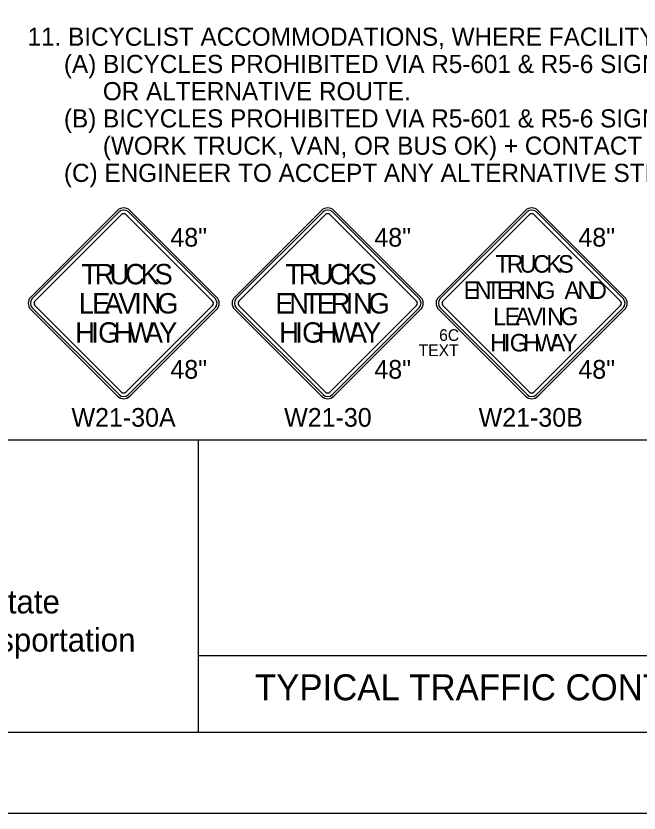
# Model space of a CAD drawing. Extents: x 99999 to 100116, y 99995 to 100013.
# Drawn here: x 100011.504 to 100013.904, y 99999.687 to 100002.761 of the extents above; entities that cross this region are included whole.
import ezdxf

# ---------------------------------------------------------------- set-up
doc = ezdxf.new("R2010")
doc.units = 0
for name, color, linetype in [('SH_GI_GeneralNotesBodyText', 7, 'Continuous'), ('SH_GI_PlotLimits', 7, 'Continuous'), ('SH_GI_SheetBorder', 7, 'Continuous'), ('SH_GI_SheetTextInCells', 7, 'Continuous'), ('SH_GI_TitleBlockText', 7, 'Continuous'), ('TR_SN_ConstructionSigns', 7, 'Continuous')]:
    doc.layers.add(name, color=color, linetype=linetype)

msp = doc.modelspace()

# ---------------------------------------------------------------- linework, layer by layer
at = {"layer": 'SH_GI_PlotLimits'}
msp.add_lwpolyline([(99999.0625, 99999.6875), (100016.0625, 99999.6875), (100016.0625, 100010.6875), (99999.0625, 100010.6875)], close=True, dxfattribs=at)
at = {"layer": 'SH_GI_SheetBorder'}
for p, q in [((100000, 100001.1259), (100015.75, 100001.1259)), ((100012.2055, 100001.1259), (100012.2055, 100000)), ((100012.2055, 100000.2955), (100015.2079, 100000.2955)), ((100000, 100000), (100015.75, 100000))]:
    msp.add_line(p, q, dxfattribs=at)
at = {"layer": 'TR_SN_ConstructionSigns'}
for p, q in [((100011.8955, 100002.0107), (100011.5613, 100001.6766)), ((100011.9014, 100002.0048), (100011.5673, 100001.6707)), ((100011.5773, 100001.6607), (100011.9114, 100001.9948)), ((100011.9273, 100001.9948), (100012.2614, 100001.6607)), ((100012.2713, 100001.6707), (100011.9372, 100002.0048)), ((100012.2773, 100001.6766), (100011.9432, 100002.0107)), ((100012.6812, 100002.0107), (100012.3471, 100001.6766)), ((100012.6871, 100002.0048), (100012.353, 100001.6707)), ((100012.363, 100001.6607), (100012.6971, 100001.9948)), ((100012.713, 100001.9948), (100013.0471, 100001.6607)), ((100013.057, 100001.6707), (100012.7229, 100002.0048)), ((100013.063, 100001.6766), (100012.7289, 100002.0107)), ((100013.4669, 100002.0107), (100013.1328, 100001.6766)), ((100013.4729, 100002.0048), (100013.1387, 100001.6707)), ((100013.1487, 100001.6607), (100013.4828, 100001.9948)), ((100013.4987, 100001.9948), (100013.8328, 100001.6607)), ((100013.8428, 100001.6707), (100013.5087, 100002.0048)), ((100013.8487, 100001.6766), (100013.5146, 100002.0107)), ((100011.5613, 100001.6289), (100011.8955, 100001.2948)), ((100011.5673, 100001.6349), (100011.9014, 100001.3008)), ((100011.9114, 100001.3107), (100011.5773, 100001.6448)), ((100012.2614, 100001.6448), (100011.9273, 100001.3107)), ((100011.9372, 100001.3008), (100012.2713, 100001.6349)), ((100011.9432, 100001.2948), (100012.2773, 100001.6289)), ((100012.3471, 100001.6289), (100012.6812, 100001.2948)), ((100012.353, 100001.6349), (100012.6871, 100001.3008)), ((100012.6971, 100001.3107), (100012.363, 100001.6448)), ((100013.0471, 100001.6448), (100012.713, 100001.3107)), ((100012.7229, 100001.3008), (100013.057, 100001.6349)), ((100012.7289, 100001.2948), (100013.063, 100001.6289)), ((100013.1328, 100001.6289), (100013.4669, 100001.2948)), ((100013.1387, 100001.6349), (100013.4729, 100001.3008)), ((100013.4828, 100001.3107), (100013.1487, 100001.6448)), ((100013.8328, 100001.6448), (100013.4987, 100001.3107)), ((100013.5087, 100001.3008), (100013.8428, 100001.6349)), ((100013.5146, 100001.2948), (100013.8487, 100001.6289))]:
    msp.add_line(p, q, dxfattribs=at)
for centre, radius, start, end in [((100011.9193, 100001.9869), 0.0338, 45, 135), ((100011.9193, 100001.9869), 0.0253, 45, 135), ((100011.9193, 100001.9869), 0.0113, 45, 135), ((100012.705, 100001.9869), 0.0338, 45, 135), ((100012.705, 100001.9869), 0.0253, 45, 135), ((100012.705, 100001.9869), 0.0113, 45, 135), ((100013.4908, 100001.9869), 0.0338, 45, 135), ((100013.4908, 100001.9869), 0.0253, 45, 135), ((100013.4908, 100001.9869), 0.0113, 45, 135), ((100011.5852, 100001.6528), 0.0338, 135, 225), ((100011.5852, 100001.6528), 0.0253, 135, 225), ((100011.5852, 100001.6528), 0.0113, 135, 225), ((100012.2534, 100001.6528), 0.0113, 315, 45), ((100012.2534, 100001.6528), 0.0253, 315, 45), ((100012.2534, 100001.6528), 0.0338, 315, 45), ((100012.3709, 100001.6528), 0.0338, 135, 225), ((100012.3709, 100001.6528), 0.0253, 135, 225), ((100012.3709, 100001.6528), 0.0113, 135, 225), ((100013.0391, 100001.6528), 0.0113, 315, 45), ((100013.0391, 100001.6528), 0.0253, 315, 45), ((100013.0391, 100001.6528), 0.0338, 315, 45), ((100013.1566, 100001.6528), 0.0338, 135, 225), ((100013.1566, 100001.6528), 0.0253, 135, 225), ((100013.1566, 100001.6528), 0.0113, 135, 225), ((100013.8249, 100001.6528), 0.0113, 315, 45), ((100013.8249, 100001.6528), 0.0253, 315, 45), ((100013.8249, 100001.6528), 0.0338, 315, 45), ((100011.9193, 100001.3187), 0.0338, 225, 315), ((100011.9193, 100001.3187), 0.0253, 225, 315), ((100011.9193, 100001.3187), 0.0113, 225, 315), ((100012.705, 100001.3187), 0.0338, 225, 315), ((100012.705, 100001.3187), 0.0253, 225, 315), ((100012.705, 100001.3187), 0.0113, 225, 315), ((100013.4908, 100001.3187), 0.0338, 225, 315), ((100013.4908, 100001.3187), 0.0253, 225, 315), ((100013.4908, 100001.3187), 0.0113, 225, 315)]:
    msp.add_arc(centre, radius, start, end, dxfattribs=at)

# ---------------------------------------------------------------- texts
at = {"layer": 'SH_GI_GeneralNotesBodyText'}
for s, p in [('11. BICYCLIST ACCOMMODATIONS, WHERE FACILITY OPEN TO BICYCLES:', (100011.549, 100002.6456)), ('(A) BICYCLES PROHIBITED VIA R5-601 & R5-6 SIGNS. PROVIDE SIGNED DETOUR ', (100011.689, 100002.5406)), ('OR ALTERNATIVE ROUTE.', (100011.839, 100002.4356)), ('(B) BICYCLES PROHIBITED VIA R5-601 & R5-6 SIGNS. PROVIDE FREE SHUTTLE ', (100011.689, 100002.3306)), ('(WORK TRUCK, VAN, OR BUS OK) + CONTACT INFORMATION OR PHONE BOX.', (100011.839, 100002.2256)), ('(C) ENGINEER TO ACCEPT ANY ALTERNATIVE STRATEGIES.', (100011.689, 100002.1206))]:
    msp.add_text(s, height=0.07, rotation=360, dxfattribs=at).set_placement(p)
at = {"layer": 'SH_GI_SheetTextInCells'}
for s, p in [('Washington State', (100010.7229, 100000.4571)), ('Department of Transportation', (100010.3916, 100000.3101))]:
    msp.add_text(s, height=0.090072, dxfattribs=at).set_placement(p)
at = {"layer": 'SH_GI_TitleBlockText'}
msp.add_text('TYPICAL TRAFFIC CONTROL PLANS', height=0.1, dxfattribs=at).set_placement((100012.4251, 100000.1224))
at = {"layer": 'TR_SN_ConstructionSigns'}
for s, p in [('48"', (100012.0991, 100001.8713)), ('48"', (100012.8848, 100001.8713)), ('48"', (100013.6706, 100001.8713)), ('48"', (100012.0991, 100001.3622)), ('48"', (100012.8848, 100001.3622)), ('48"', (100013.6706, 100001.3622)), ('W21-30A', (100011.7182, 100001.1769)), ('W21-30', (100012.5373, 100001.1769)), ('W21-30B', (100013.2863, 100001.1769))]:
    msp.add_text(s, height=0.072, rotation=360, dxfattribs=at).set_placement(p)
for s, height, p in [('T', 0.0675, (100013.351, 100001.7709)), ('R', 0.0675, (100013.3949, 100001.7709)), ('U', 0.0675, (100013.4442, 100001.7709)), ('C', 0.0675, (100013.4955, 100001.7709)), ('K', 0.0675, (100013.5468, 100001.7709)), ('S', 0.0675, (100013.5927, 100001.7709)), ('T', 0.0787, (100011.7563, 100001.7259)), ('R', 0.0787, (100011.8075, 100001.7259)), ('U', 0.0787, (100011.865, 100001.7259)), ('C', 0.0787, (100011.9248, 100001.7259)), ('K', 0.0787, (100011.9847, 100001.7259)), ('S', 0.0787, (100012.0382, 100001.7259)), ('T', 0.0787, (100012.542, 100001.7259)), ('R', 0.0787, (100012.5932, 100001.7259)), ('U', 0.0787, (100012.6507, 100001.7259)), ('C', 0.0787, (100012.7106, 100001.7259)), ('K', 0.0787, (100012.7704, 100001.7259)), ('S', 0.0787, (100012.824, 100001.7259)), ('E', 0.0675, (100013.2286, 100001.6696)), ('N', 0.0675, (100013.271, 100001.6696)), ('T', 0.0675, (100013.3154, 100001.6696)), ('E', 0.0675, (100013.3565, 100001.6696)), ('R', 0.0675, (100013.3989, 100001.6696)), ('I', 0.0675, (100013.4448, 100001.6696)), ('N', 0.0675, (100013.4646, 100001.6696)), ('G', 0.0675, (100013.5118, 100001.6696)), ('A', 0.0675, (100013.6171, 100001.6696)), ('N', 0.0675, (100013.667, 100001.6696)), ('D', 0.0675, (100013.7152, 100001.6696)), ('L', 0.0787, (100011.7465, 100001.6134)), ('E', 0.0787, (100011.7977, 100001.6134)), ('A', 0.0787, (100011.8449, 100001.6134)), ('V', 0.0787, (100011.9, 100001.6134)), ('I', 0.0787, (100011.9599, 100001.6134)), ('N', 0.0787, (100011.9882, 100001.6134)), ('G', 0.0787, (100012.0481, 100001.6134)), ('E', 0.0787, (100012.5034, 100001.6134)), ('N', 0.0787, (100012.557, 100001.6134)), ('T', 0.0787, (100012.6121, 100001.6134)), ('E', 0.0787, (100012.6633, 100001.6134)), ('R', 0.0787, (100012.7169, 100001.6134)), ('I', 0.0787, (100012.7743, 100001.6134)), ('N', 0.0787, (100012.8027, 100001.6134)), ('G', 0.0787, (100012.8625, 100001.6134)), ('L', 0.0675, (100013.3426, 100001.5684)), ('E', 0.0675, (100013.3865, 100001.5684)), ('A', 0.0675, (100013.427, 100001.5684)), ('V', 0.0675, (100013.4742, 100001.5684)), ('I', 0.0675, (100013.5255, 100001.5684)), ('N', 0.0675, (100013.5498, 100001.5684)), ('G', 0.0675, (100013.6011, 100001.5684)), ('H', 0.0787, (100011.7327, 100001.5009)), ('I', 0.0787, (100011.7941, 100001.5009)), ('G', 0.0787, (100011.8209, 100001.5009)), ('H', 0.0787, (100011.8807, 100001.5009)), ('W', 0.0787, (100011.9359, 100001.5009)), ('A', 0.0787, (100012.0004, 100001.5009)), ('Y', 0.0787, (100012.0556, 100001.5009)), ('H', 0.0787, (100012.5184, 100001.5009)), ('I', 0.0787, (100012.5798, 100001.5009)), ('G', 0.0787, (100012.6066, 100001.5009)), ('H', 0.0787, (100012.6665, 100001.5009)), ('W', 0.0787, (100012.7216, 100001.5009)), ('A', 0.0787, (100012.7862, 100001.5009)), ('Y', 0.0787, (100012.8413, 100001.5009)), ('6C', 0.045, (100013.1343, 100001.5077)), ('H', 0.0675, (100013.3308, 100001.4671)), ('I', 0.0675, (100013.3834, 100001.4671)), ('G', 0.0675, (100013.4064, 100001.4671)), ('H', 0.0675, (100013.4577, 100001.4671)), ('W', 0.0675, (100013.5049, 100001.4671)), ('A', 0.0675, (100013.5603, 100001.4671)), ('Y', 0.0675, (100013.6075, 100001.4671)), ('TEXT', 0.045, (100013.0554, 100001.4491))]:
    msp.add_text(s, height=height, dxfattribs=at).set_placement(p)

doc.saveas('drawing.dxf')
